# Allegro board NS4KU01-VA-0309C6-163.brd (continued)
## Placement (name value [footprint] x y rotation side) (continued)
M3  -  [M-MARK1]  58.34 139.41 0 top
M4  -  [M-MARK1]  36.34 18.21 0 top
M5  -  [M-MARK1]  137.11 31.49 0 top
M6  -  [M-MARK1]  151.3 138.56 0 top
M9  -  [M-MARK1]  151.56 138.56 180 bottom
M10  -  [M-MARK1]  6.9 138.56 180 bottom
M13  -  [M-MARK1]  13.74 15.61 180 bottom
M14  -  [M-MARK1]  137.16 20.69 180 bottom
NOREF  -  []  2.69 55.3 0 top
NOREF#2  -  [unnamed#2]  138.17 4 0 top
NOREF#3  -  [unnamed#2]  145.37 4 0 top
NOREF#4  -  [unnamed#2]  -5.27 11.02 0 top
NOREF#5  -  [unnamed#2]  0.73 9.02 0 top
NOREF#6  -  [unnamed#2]  4.64 4.18 0 top
NOREF#7  -  [unnamed#2]  5.84 6.14 0 top
NOREF#8  -  [unnamed#2]  140.57 6 0 top
NOREF#9  -  [unnamed#2]  136.97 4 0 top
NOREF#10  -  [unnamed#2]  -7.67 11.02 0 top
NOREF#11  -  [unnamed#2]  139.37 6 0 top
NOREF#12  -  [unnamed#2]  144.17 4 0 top
NOREF#13  -  [unnamed#2]  4.64 6.14 0 top
NOREF#14  -  [unnamed#2]  144.17 6 0 top
NOREF#15  -  [unnamed#2]  -8.87 9.02 0 top
NOREF#16  -  [unnamed#2]  142.97 4 0 top
NOREF#17  -  [unnamed#2]  -0.47 11.02 0 top
NOREF#18  -  [unnamed#2]  139.37 4 0 top
NOREF#19  -  [unnamed#2]  -8.87 11.02 0 top
NOREF#20  -  [unnamed#2]  158.69 8.2 0 top
NOREF#21  -  [unnamed#2]  146.57 4 0 top
NOREF#22  -  [unnamed#2]  -4.07 11.02 0 top
NOREF#23  -  [unnamed#2]  136.97 6 0 top
NOREF#24  -  []  43.24 -116.05 0 top
NOREF#25  -  [unnamed#2]  -2.87 9.02 0 top
NOREF#26  -  [unnamed#2]  140.57 4 0 top
NOREF#27  -  [unnamed#2]  138.17 6 0 top
NOREF#28  -  [unnamed#2]  146.57 6 0 top
NOREF#29  -  [unnamed#2]  -1.67 9.02 0 top
NOREF#30  -  [unnamed#2]  7.04 4.18 0 top
NOREF#31  -  [unnamed#2]  141.77 4 0 top
NOREF#32  -  [unnamed#2]  -7.67 9.02 0 top
NOREF#33  -  [unnamed#2]  145.37 6 0 top
NOREF#34  -  [unnamed#2]  -4.07 9.02 0 top
NOREF#35  -  [unnamed#2]  142.97 6 0 top
NOREF#36  -  [unnamed#2]  0.73 11.02 0 top
NOREF#37  -  [unnamed#2]  -6.47 11.02 0 top
NOREF#38  -  [unnamed#2]  -1.67 11.02 0 top
NOREF#39  -  [unnamed#2]  7.04 6.14 0 top
NOREF#40  -  [unnamed#2]  -6.47 9.02 0 top
NOREF#41  -  [unnamed#2]  -0.47 9.02 0 top
NOREF#42  -  [unnamed#2]  72.19 139.9 0 top
NOREF#43  -  [unnamed#2]  -2.87 11.02 0 top
NOREF#44  -  [unnamed#2]  141.77 6 0 top
NOREF#45  -  [unnamed#2]  134.41 9.53 0 top
NOREF#46  -  [unnamed#2]  -5.27 9.02 0 top
NOREF#47  -  [unnamed#2]  5.84 4.18 0 top
NOREF#48  -  []  2.69 55.3 180 bottom
PJP2  -  [TOPSHORT_20X30]  18.33 102.04 90 top
PJP6  -  [TOPSHORT_20X30]  46 139.5 180 top
PJP10  -  [TOPSHORT_20X30]  102.28 139.83 90 top
PJP11  -  [TOPSHORT_20X30]  58.57 137.15 270 bottom
PJP12  -  [TOPSHORT_20X30]  130.42 116.13 90 top
PJP17  -  [TOPOPEN_20X157]  68.78 76.21 0 bottom
PJP18  -  [TOPOPEN_20X157]  78.18 75.83 180 bottom
PJP36  -  [TOPSHORT_20X30]  22.44 44.31 90 bottom
PS3  SPR-P110-6V-1.1A-0805  [M-C0805]  144.19 106.69 90 top
Q1  MTDK5S6R-0-T1-G  [SOT363]  3.66 107.73 0 bottom
Q4  2N7002-7-F  [M-SOT23G]  54.38 59.55 0 top
Q6  LMBT3904LT1G  [M-SOT23A]  62.15 58.55 270 top
Q10  -  [M-SC70-5]  115.23 57.03 90 top
Q11  MTDK5S6R-0-T1-G  [SOT363]  107.49 59.6 0 top
Q12  2N7002-7-F  [M-SOT23G]  120.15 138.52 0 top
Q13  LMBT3904LT1G  [M-SOT23A]  117.98 53.83 90 top
Q14  2N7002-7-F  [M-SOT23G]  118.11 130.58 180 top
Q15  MTDK5S6R-0-T1-G  [SOT363]  124.61 74.48 0 top
Q16  MTDK5S6R-0-T1-G  [SOT363]  125.24 119.69 0 bottom
Q17  -  [M-SC70-5]  17.97 116.44 270 top
Q18  MTDK5S6R-0-T1-G  [SOT363]  128.6 136.28 0 bottom
Q19  2N7002-7-F  [M-SOT23G]  144.19 20.84 90 top
Q20  2N7002-7-F  [M-SOT23G]  30.19 79.17 0 top
Q21  @LMBT3904LT1G  [M-SOT23A]  119.48 138.44 270 bottom
Q22  @LMBT3904LT1G  [M-SOT23A]  113.46 138.44 90 bottom
Q24  MTDK5S6R-0-T1-G  [SOT363]  125.27 137.04 90 bottom
Q25  MTDK5S6R-0-T1-G  [SOT363]  108.58 135.94 90 bottom
Q26  2N7002-7-F  [M-SOT23G]  126.79 132.21 90 bottom
Q27  MTDK5S6R-0-T1-G  [SOT363]  130.6 119.77 180 bottom
Q28  2N7002-7-F  [M-SOT23G]  145.97 104.02 90 bottom
Q29  2N7002-7-F  [M-SOT23G]  145.97 100.85 90 bottom
Q30  2N7002-7-F  [M-SOT23G]  110.92 99.58 0 bottom
Q31  EMB20N03V  [PDFN-8P_B3X3_D65]  6.43 98.89 0 bottom
Q32  2N7002-7-F  [M-SOT23G]  145.97 97.54 90 bottom
Q33  2N7002-7-F  [M-SOT23G]  148 93.73 90 bottom
Q34  EMB20N03V  [PDFN-8P_B3X3_D65]  10.03 92.29 0 bottom
Q35  2N7002-7-F  [M-SOT23G]  17.61 65.58 0 top
Q36  2N7002-7-F  [M-SOT23G]  22.16 72.45 270 bottom
Q37  2N7002-7-F  [M-SOT23G]  22.79 69.09 90 bottom
Q38  2N7002-7-F  [M-SOT23G]  110.66 51.44 90 bottom
Q39  MTDK5S6R  [SOT363]  142.11 50.78 180 bottom
Q40  2N7002-7-F  [M-SOT23G]  143.55 31.63 180 bottom
Q41  EMB20N03V  [PDFN-8P_B3X3_D65]  73.45 34.3 180 top
Q42  EMB20N03V  [PDFN-8P_B3X3_D65]  78.15 34.3 0 top
Q43  -  [PQFN8-PPS]  56.21 39.89 90 top
Q44  -  [PQFN8-PPS]  64.69 35.57 0 top
Q45  -  [PQFN8-PPS]  28.24 65.97 90 top
Q46  -  [PQFN8-PPS]  34.67 66.07 180 top
Q47  EMB20N03V  [PDFN-8P_B3X3_D65]  88.08 37.86 90 top
Q48  EMB20N03V  [PDFN-8P_B3X3_D65]  96.21 37.47 0 top
Q49  2N7002-7-F  [M-SOT23G]  138.66 70.72 180 bottom
Q50  2N7002-7-F  [M-SOT23G]  138.63 66.99 180 bottom
Q51  2N7002-7-F  [M-SOT23G]  132.12 106.69 0 bottom
Q52  2N7002-7-F  [M-SOT23G]  123.69 138.24 270 top
Q53  2N7002-7-F  [M-SOT23G]  140.87 58.86 90 bottom
Q54  2N7002-7-F  [M-SOT23G]  134.01 72.06 270 top
Q55  LMBT3904LT1G  [M-SOT23A]  102.36 138.28 0 bottom
Q56  2N7002-7-F  [M-SOT23G]  99.09 136.25 0 bottom
Q57  2N7002-7-F  [M-SOT23G]  140.12 95.01 0 bottom
Q58  2N7002-7-F  [M-SOT23G]  140.08 100.02 180 bottom
Q59  MTDK5S6R  [SOT363]  132.15 76.59 180 top
Q60  -  [PQFN8-PPS]  48.46 40.01 270 top
Q61  EMB20N03V  [PDFN-8P_B3X3_D65]  140.63 107.96 270 top
Q62  -  [PQFN8-PPS]  42.62 47 270 top
Q63  -  [PQFN8-PPS]  42.63 46.98 90 bottom
Q151  2N7002-7-F  [M-SOT23G]  12.79 47.61 180 top
Q152  2N7002-7-F  [M-SOT23G]  9.55 47.61 180 top
Q156  VALUE*  [M-SOT23A]  26.91 79.17 0 top
R1  499-1-04  [M-R0402]  6.43 102.57 0 bottom
R2  499-1-04  [M-R0402]  5.51 108.23 90 bottom
R3  499-1-04  [M-R0402]  1.85 106.2 90 bottom
R4  499-1-04  [M-R0402]  3.73 110.49 90 bottom
R5  499-1-04  [M-R0402]  4.17 104.34 180 bottom
R6  499-1-04  [M-R0402]  8.3 97.67 270 top
R7  499-1-04  [M-R0402]  10.08 98.31 0 top
R8  499-1-04  [M-R0402]  10.2 99.96 270 top
R9  499-1-04  [M-R0402]  11.73 99.45 270 top
R10  499-1-04  [M-R0402]  11.98 128.4 0 top
R11  499-1-04  [M-R0402]  11.98 126.12 0 top
R12  499-1-04  [M-R0402]  11.98 125.1 180 top
R13  499-1-04  [M-R0402]  12.74 99.45 270 top
R14  499-1-04  [M-R0402]  13.89 99.45 270 top
R15  @1K-1-06  [M-R0603]  14.9 62.18 180 top
R16  @1K-1-06  [M-R0603]  14.9 60.75 180 top
R17  @1K-1-06  [M-R0603]  15.08 100.26 90 top
R18  499-1-04  [M-R0402]  20.14 114.77 0 top
R19  499-1-04  [M-R0402]  16.3 131.33 90 top
R20  @1K-1-06  [M-R0603]  16.48 100.26 90 top
R21  499-1-04  [M-R0402]  16.91 62.16 270 top
R22  499-1-04  [M-R0402]  16.79 118.8 180 top
R23  499-1-04  [M-R0402]  20.22 62.16 270 top
R24  499-1-04  [M-R0402]  18.71 131.33 270 top
R25  @1K-1-06  [M-R0603]  18.84 99.07 270 top
R26  @1K-1-06  [M-R0603]  19.35 91.83 0 top
R27  499-1-04  [M-R0402]  23.64 62.16 270 top
R28  499-1-04  [M-R0402]  19.73 131.33 90 top
R29  499-1-04  [M-R0402]  19.73 97.16 180 top
R30  499-1-04  [M-R0402]  19.73 95.89 0 top
R31  499-1-04  [M-R0402]  20.24 99.32 90 top
R32  499-1-04  [M-R0402]  12.82 113.67 0 top
R33  499-1-04  [M-R0402]  20.87 119.77 0 top
R34  499-1-04  [M-R0402]  20.87 118.75 180 top
R35  499-1-04  [M-R0402]  20.87 117.74 180 top
R36  499-1-04  [M-R0402]  23.54 125.36 0 top
R37  499-1-04  [M-R0402]  23.54 124.34 0 top
R38  499-1-04  [M-R0402]  25.19 125.61 270 top
R41  499-1-04  [M-R0402]  17.01 85.38 90 bottom
R42  499-1-04  [M-R0402]  142.95 26.29 0 top
R43  @1K-1-06  [M-R0603]  29.99 125.38 270 top
R46  @1K-1-06  [M-R0603]  33.04 124.77 180 top
R50  499-1-04  [M-R0402]  142.87 45.8 0 top
R51  @1K-1-06  [M-R0603]  36.62 129.29 0 top
R52  499-1-04  [M-R0402]  18.49 133.18 180 bottom
R53  499-1-04  [M-R0402]  39.9 130.61 270 top
R54  499-1-04  [M-R0402]  16.2 133.18 180 bottom
R55  @1K-1-06  [M-R0603]  143.91 52.51 270 bottom
R56  499-1-04  [M-R0402]  23.57 133.36 180 bottom
R57  499-1-04  [M-R0402]  25.85 133.36 180 bottom
R58  499-1-04  [M-R0402]  116.79 22.11 0 bottom
R59  499-1-04  [M-R0402]  43.92 138.95 90 top
R60  499-1-04  [M-R0402]  42.06 129.85 270 top
R61  499-1-04  [M-R0402]  119.07 22.11 180 bottom
R62  499-1-04  [M-R0402]  116.79 18.68 0 bottom
R63  499-1-04  [M-R0402]  45.49 130.1 90 top
R64  499-1-04  [M-R0402]  119.07 18.68 180 bottom
R65  499-1-04  [M-R0402]  125.68 23.25 90 top
R66  499-1-04  [M-R0402]  87.33 129.46 180 bottom
R67  499-1-04  [M-R0402]  89.05 128.83 90 bottom
R68  499-1-04  [M-R0402]  90.26 128.83 270 bottom
R69  499-1-04  [M-R0402]  57.83 89.06 270 bottom
R70  499-1-04  [M-R0402]  53.96 89.12 270 bottom
R71  499-1-04  [M-R0402]  52.16 88.57 0 bottom
R72  499-1-04  [M-R0402]  55.8 90.83 0 bottom
R73  499-1-04  [M-R0402]  52.16 89.78 180 bottom
R74  499-1-04  [M-R0402]  39.16 93.88 0 bottom
R75  499-1-04  [M-R0402]  38.78 82.39 0 top
R76  499-1-04  [M-R0402]  37.74 100.83 0 top
R77  499-1-04  [M-R0402]  38.84 112.93 180 bottom
R79  499-1-04  [M-R0402]  63.35 63.89 0 bottom
R80  499-1-04  [M-R0402]  54.44 57.14 180 top
R81  499-1-04  [M-R0402]  36.18 94.96 90 bottom
R82  499-1-04  [M-R0402]  55.72 61.37 90 top
R83  499-1-04  [M-R0402]  56.94 58.94 270 top
R85  499-1-04  [M-R0402]  57.96 58.94 90 top
R86  499-1-04  [M-R0402]  56.92 61.37 270 top
R87  499-1-04  [M-R0402]  37.38 94.96 90 bottom
R88  499-1-04  [M-R0402]  58.06 61.35 270 bottom
R89  499-1-04  [M-R0402]  58.98 58.93 270 bottom
R90  499-1-04  [M-R0402]  131.41 112.37 180 top
R91  499-1-04  [M-R0402]  133.89 112.29 180 top
R92  499-1-04  [M-R0402]  61.26 61.35 90 top
R93  499-1-04  [M-R0402]  34.12 94.67 0 top
R94  499-1-04  [M-R0402]  62.4 61.35 270 top
R95  499-1-04  [M-R0402]  63.42 61.35 270 top
R96  499-1-04  [M-R0402]  133.85 110.09 0 top
R97  499-1-04  [M-R0402]  133.89 111.27 180 top
R98  499-1-04  [M-R0402]  65.58 61.35 270 top
R99  499-1-04  [M-R0402]  65.7 58.81 270 top
R100  499-1-04  [M-R0402]  66.72 61.35 90 top
R101  499-1-04  [M-R0402]  66.72 58.81 90 top
R102  @1K-1-06  [M-R0603]  66.72 57.03 0 top
R103  499-1-04  [M-R0402]  67.86 61.35 90 top
R104  499-1-04  [M-R0402]  67.86 58.81 270 top
R105  499-1-04  [M-R0402]  70.02 61.4 90 top
R106  @1K-1-06  [M-R0603]  71.65 131.25 180 top
R107  499-1-04  [M-R0402]  119.07 19.82 180 bottom
R108  499-1-04  [M-R0402]  76.37 59.55 270 top
R109  499-1-04  [M-R0402]  81.2 60.71 180 top
R110  499-1-04  [M-R0402]  87.73 50.68 180 top
R111  499-1-04  [M-R0402]  119.07 20.96 180 bottom
R112  499-1-04  [M-R0402]  87.73 51.95 0 top
R113  499-1-04  [M-R0402]  113.84 59.06 180 top
R114  499-1-04  [M-R0402]  90.47 139.07 0 top
R115  499-1-04  [M-R0402]  100.1 139.12 90 bottom
R116  499-1-04  [M-R0402]  11.99 115.22 180 top
R117  499-1-04  [M-R0402]  116.12 59.06 180 top
R118  499-1-04  [M-R0402]  93.04 61.35 270 top
R119  499-1-04  [M-R0402]  118.41 58.3 0 top
R120  499-1-04  [M-R0402]  119.07 17.54 180 bottom
R121  499-1-04  [M-R0402]  94.28 61.35 90 top
R122  499-1-04  [M-R0402]  94.94 133.28 270 top
R123  499-1-04  [M-R0402]  95.42 61.35 90 top
R124  499-1-04  [M-R0402]  96.56 61.35 90 top
R125  @1K-1-06  [M-R0603]  96.59 52.71 270 top
R126  499-1-04  [M-R0402]  97.71 61.35 90 top
R127  499-1-04  [M-R0402]  102.03 61.35 90 top
R128  499-1-04  [M-R0402]  99.56 61.32 270 top
R129  499-1-04  [M-R0402]  99.99 138.82 180 top
R130  499-1-04  [M-R0402]  100.12 135.9 180 top
R131  499-1-04  [M-R0402]  103.17 61.35 270 top
R132  499-1-04  [M-R0402]  110.9 9.22 90 top
R133  499-1-04  [M-R0402]  111.98 9.22 90 top
R134  499-1-04  [M-R0402]  113.16 9.21 90 top
R135  499-1-04  [M-R0402]  104.82 87.08 0 top
R136  499-1-04  [M-R0402]  104.82 85.86 180 top
R138  499-1-04  [M-R0402]  104.95 74.81 0 top
R139  499-1-04  [M-R0402]  104.82 66.94 180 top
R140  499-1-04  [M-R0402]  34.5 98.86 90 bottom
R141  499-1-04  [M-R0402]  104.95 73.16 0 top
R142  499-1-04  [M-R0402]  104.95 72.14 0 top
R143  499-1-04  [M-R0402]  104.95 71.13 180 top
R144  499-1-04  [M-R0402]  104.47 63.51 270 top
R145  @1K-1-06  [M-R0603]  105.28 53.66 270 top
R147  499-1-04  [M-R0402]  106.47 69.1 90 top
R148  499-1-04  [M-R0402]  106.72 62.49 90 top
R149  499-1-04  [M-R0402]  106.85 56.9 90 top
R150  499-1-04  [M-R0402]  106.98 87.38 90 top
R151  499-1-04  [M-R0402]  108.12 74.86 0 top
R152  499-1-04  [M-R0402]  107.23 71.13 0 top
R153  499-1-04  [M-R0402]  107.23 66.56 180 top
R154  499-1-04  [M-R0402]  107.31 65.06 0 top
R155  499-1-04  [M-R0402]  107.36 73.16 180 top
R157  499-1-04  [M-R0402]  107.87 62.49 270 top
R158  499-1-04  [M-R0402]  107.99 56.9 90 top
R159  499-1-04  [M-R0402]  108.12 87.41 270 top
R160  499-1-04  [M-R0402]  108.38 90.18 0 top
R161  499-1-04  [M-R0402]  108.5 89.03 0 top
R163  499-1-04  [M-R0402]  109.01 62.49 270 top
R164  499-1-04  [M-R0402]  109.5 56.82 270 top
R165  @1K-1-06  [M-R0603]  104.66 130.82 180 top
R167  499-1-04  [M-R0402]  111.3 72.02 90 top
R168  499-1-04  [M-R0402]  110.28 75.06 90 top
R170  499-1-04  [M-R0402]  111.3 75.06 270 top
R171  499-1-04  [M-R0402]  112.31 72.02 90 top
R173  499-1-04  [M-R0402]  110.15 72.02 90 top
R174  499-1-04  [M-R0402]  120.78 134.61 0 top
R176  499-1-04  [M-R0402]  113.33 72.02 270 top
R177  499-1-04  [M-R0402]  113.69 74.86 270 top
R179  499-1-04  [M-R0402]  114.83 74.86 270 top
R180  499-1-04  [M-R0402]  114.85 73.41 180 top
R182  @1K-1-06  [M-R0603]  117.98 132.97 180 top
R184  499-1-04  [M-R0402]  118.33 139.86 0 top
R185  499-1-04  [M-R0402]  117.55 91.85 0 top
R187  499-1-04  [M-R0402]  117.77 99.7 0 top
R188  499-1-04  [M-R0402]  117.77 98.56 0 top
R189  499-1-04  [M-R0402]  115.8 131.67 270 top
R190  499-1-04  [M-R0402]  119.3 80.53 90 top
R191  499-1-04  [M-R0402]  119.3 92.97 0 top
R192  499-1-04  [M-R0402]  119.42 75.83 270 top
R193  499-1-04  [M-R0402]  119.42 73.67 90 top
R194  499-1-04  [M-R0402]  140.6 61.12 0 bottom
R195  499-1-04  [M-R0402]  120.31 98.56 0 top
R196  499-1-04  [M-R0402]  120.57 75.83 270 top
R197  499-1-04  [M-R0402]  120.57 74.94 270 top
R198  @1K-1-06  [M-R0603]  123.95 112.35 0 bottom
R199  499-1-04  [M-R0402]  121.53 53.7 270 top
R200  499-1-04  [M-R0402]  121.72 75.83 90 top
R201  499-1-04  [M-R0402]  121.72 74.94 90 top
R202  499-1-04  [M-R0402]  122.47 72.65 90 top
R204  499-1-04  [M-R0402]  124.12 72.14 0 top
R205  499-1-04  [M-R0402]  124.79 76.94 180 top
R207  499-1-04  [M-R0402]  115.23 122.65 180 bottom
R210  499-1-04  [M-R0402]  128.12 119.65 180 top
R211  499-1-04  [M-R0402]  125.69 71.63 90 top
R212  499-1-04  [M-R0402]  122.86 74.93 270 top
R213  499-1-04  [M-R0402]  126.28 63.25 0 top
R214  499-1-04  [M-R0402]  126.28 62.24 0 top
R215  499-1-04  [M-R0402]  109.5 59.11 90 top
R216  499-1-04  [M-R0402]  126.54 60.33 90 top
R217  499-1-04  [M-R0402]  126.92 67.32 270 top
R218  499-1-04  [M-R0402]  127.55 60.33 90 top
R219  499-1-04  [M-R0402]  128.19 118.5 0 top
R220  499-1-04  [M-R0402]  119.53 115.12 270 bottom
R221  499-1-04  [M-R0402]  142.15 70.42 270 bottom
R222  499-1-04  [M-R0402]  128.17 113.85 0 top
R223  499-1-04  [M-R0402]  128.47 80.86 90 top
R224  499-1-04  [M-R0402]  128.47 79.99 90 top
R225  499-1-04  [M-R0402]  128.57 60.33 90 top
R226  499-1-04  [M-R0402]  82.21 124.43 180 bottom
R227  499-1-04  [M-R0402]  94.21 125.44 180 bottom
R228  499-1-04  [M-R0402]  128.42 119.18 270 bottom
R229  499-1-04  [M-R0402]  129.58 60.33 270 top
R230  @1K-1-06  [M-R0603]  112.69 119.92 90 bottom
R231  499-1-04  [M-R0402]  128.29 116.21 0 top
R232  499-1-04  [M-R0402]  130.51 80.86 90 top
R233  499-1-04  [M-R0402]  130.51 79.99 90 top
R234  499-1-04  [M-R0402]  127.28 119.18 270 bottom
R235  @1K-1-06  [M-R0603]  142.39 104.1 270 top
R236  499-1-04  [M-R0402]  141.01 70.42 270 bottom
R237  499-1-04  [M-R0402]  94.21 126.65 0 bottom
R238  499-1-04  [M-R0402]  131.65 80.86 270 top
R239  499-1-04  [M-R0402]  132.61 120.83 90 bottom
R240  499-1-04  [M-R0402]  132.67 80.86 90 top
R241  499-1-04  [M-R0402]  132.89 64.9 180 top
R242  499-1-04  [M-R0402]  132.89 63.89 180 top
R243  499-1-04  [M-R0402]  132.89 62.75 180 top
R244  499-1-04  [M-R0402]  133.75 120.83 90 bottom
R245  @1K-1-06  [M-R0603]  133.65 69.6 0 top
R246  499-1-04  [M-R0402]  113.65 124.17 90 bottom
R247  499-1-04  [M-R0402]  115.23 123.85 0 bottom
R248  499-1-04  [M-R0402]  134.66 45.98 90 top
R249  499-1-04  [M-R0402]  6.38 62.75 0 top
R250  499-1-04  [M-R0402]  131.32 113.44 90 bottom
R251  499-1-04  [M-R0402]  134.89 86.67 90 top
R252  499-1-04  [M-R0402]  134.89 85.78 270 top
R253  499-1-04  [M-R0402]  130.81 111.66 0 bottom
R254  499-1-04  [M-R0402]  112.5 124.17 270 bottom
R255  499-1-04  [M-R0402]  135.68 45.98 90 top
R256  499-1-04  [M-R0402]  36.92 100.06 90 bottom
R257  499-1-04  [M-R0402]  28.75 94.71 90 top
R258  499-1-04  [M-R0402]  136.07 70.16 90 top
R260  499-1-04  [M-R0402]  130.3 113.44 90 bottom
R261  499-1-04  [M-R0402]  136.21 86.67 90 top
R262  499-1-04  [M-R0402]  136.21 85.78 270 top
R263  499-1-04  [M-R0402]  129.94 111.66 180 bottom
R264  @1K-1-06  [M-R0603]  50.12 131.56 180 top
R265  499-1-04  [M-R0402]  136.7 45.98 90 top
R266  499-1-04  [M-R0402]  30.18 100.19 270 bottom
R267  499-1-04  [M-R0402]  28.24 99.91 270 bottom
R268  499-1-04  [M-R0402]  129.28 113.44 90 bottom
R269  499-1-04  [M-R0402]  30.52 100.42 0 top
R270  499-1-04  [M-R0402]  137.71 45.98 90 top
R271  499-1-04  [M-R0402]  29.76 94.71 90 top
R272  499-1-04  [M-R0402]  29.76 97.88 90 bottom
R273  499-1-04  [M-R0402]  126.65 135.47 270 top
R274  499-1-04  [M-R0402]  26.4 94.77 90 top
R275  499-1-04  [M-R0402]  138.73 45.98 90 top
R276  499-1-04  [M-R0402]  27.52 97.52 270 bottom
R277  499-1-04  [M-R0402]  142.42 123.03 270 top
R278  499-1-04  [M-R0402]  44.47 124.01 180 top
R279  499-1-04  [M-R0402]  24.49 97.5 90 bottom
R280  499-1-04  [M-R0402]  139.72 45.98 90 top
R281  499-1-04  [M-R0402]  27.54 94.71 90 top
R282  499-1-04  [M-R0402]  141.04 66.68 270 bottom
R283  499-1-04  [M-R0402]  142.64 68.51 270 top
R284  499-1-04  [M-R0402]  143.43 123.03 270 top
R285  499-1-04  [M-R0402]  130.42 69.05 0 top
R286  499-1-04  [M-R0402]  138.55 25.68 0 top
R287  499-1-04  [M-R0402]  136.67 78.92 90 top
R288  499-1-04  [M-R0402]  142.65 116.61 180 top
R289  499-1-04  [M-R0402]  142.65 115.6 180 top
R290  499-1-04  [M-R0402]  144.7 123.03 90 top
R291  499-1-04  [M-R0402]  145.72 123.03 90 top
R292  499-1-04  [M-R0402]  142.56 113.69 180 top
R293  499-1-04  [M-R0402]  142.56 112.68 180 top
R294  499-1-04  [M-R0402]  136.34 66.1 90 bottom
R295  499-1-04  [M-R0402]  140.61 50.73 270 top
R296  499-1-04  [M-R0402]  142.95 60 180 top
R297  499-1-04  [M-R0402]  142.92 58.83 180 top
R298  499-1-04  [M-R0402]  142.65 118.72 180 top
R299  499-1-04  [M-R0402]  142.65 117.71 180 top
R300  499-1-04  [M-R0402]  141.31 79.44 180 top
R301  499-1-04  [M-R0402]  145.08 100.46 0 top
R302  499-1-04  [M-R0402]  145.08 97.42 0 top
R303  499-1-04  [M-R0402]  145.08 94.37 0 top
R304  499-1-04  [M-R0402]  147.49 102.88 180 top
R305  499-1-04  [M-R0402]  147.49 99.96 180 top
R306  499-1-04  [M-R0402]  147.62 97.29 180 top
R307  499-1-04  [M-R0402]  147.62 92.21 180 top
R308  499-1-04  [M-R0402]  147.75 94.75 180 top
R309  499-1-04  [M-R0402]  125.42 139.3 270 bottom
R310  499-1-04  [M-R0402]  92.22 139.5 270 bottom
R311  499-1-04  [M-R0402]  90.98 139.45 90 bottom
R312  499-1-04  [M-R0402]  88.69 139.45 90 bottom
R313  499-1-04  [M-R0402]  124.15 139.36 90 bottom
R314  499-1-04  [M-R0402]  122.35 139.33 180 bottom
R315  499-1-04  [M-R0402]  96.18 139.33 180 bottom
R316  499-1-04  [M-R0402]  97.97 139.15 90 bottom
R317  499-1-04  [M-R0402]  117.01 138.56 90 bottom
R318  499-1-04  [M-R0402]  116 138.56 90 bottom
R319  499-1-04  [M-R0402]  122.35 138.31 0 bottom
R320  499-1-04  [M-R0402]  141.31 78.42 180 top
R321  499-1-04  [M-R0402]  94.79 136.79 90 bottom
R322  499-1-04  [M-R0402]  114.53 136.15 0 bottom
R323  499-1-04  [M-R0402]  109.5 138.54 270 bottom
R324  499-1-04  [M-R0402]  122.35 136.28 180 bottom
R325  499-1-04  [M-R0402]  114.53 135.06 0 bottom
R326  499-1-04  [M-R0402]  122.35 135.26 180 bottom
R327  499-1-04  [M-R0402]  108.4 138.53 90 bottom
R328  499-1-04  [M-R0402]  125.65 135.26 180 bottom
R329  @1K-1-06  [M-R0603]  36.24 136.83 270 bottom
R330  499-1-04  [M-R0402]  146.43 134.12 180 bottom
R331  499-1-04  [M-R0402]  107.21 138.54 270 bottom
R332  499-1-04  [M-R0402]  124.5 133.61 90 bottom
R333  499-1-04  [M-R0402]  122.35 133.23 180 bottom
R334  499-1-04  [M-R0402]  114.55 132.41 0 bottom
R335  499-1-04  [M-R0402]  32.15 97.02 90 bottom
R336  499-1-04  [M-R0402]  38.76 126.99 180 top
R337  499-1-04  [M-R0402]  32.05 129.29 180 bottom
R338  499-1-04  [M-R0402]  30.14 129.04 270 bottom
R339  499-1-04  [M-R0402]  27.1 129.04 90 bottom
R340  499-1-04  [M-R0402]  26.08 129.04 270 bottom
R341  499-1-04  [M-R0402]  25.25 94.77 90 top
R342  499-1-04  [M-R0402]  33.68 96.76 90 bottom
R343  499-1-04  [M-R0402]  27.03 99.91 270 bottom
R344  499-1-04  [M-R0402]  35.71 98.86 90 bottom
R345  499-1-04  [M-R0402]  35.67 96.8 180 bottom
R346  499-1-04  [M-R0402]  135.55 126.5 270 bottom
R347  499-1-04  [M-R0402]  134.41 126.5 90 bottom
R348  499-1-04  [M-R0402]  128.19 126.5 270 bottom
R349  499-1-04  [M-R0402]  129.2 126.5 270 bottom
R350  499-1-04  [M-R0402]  26.08 125.74 0 bottom
R351  499-1-04  [M-R0402]  124.63 123.83 180 bottom
R352  499-1-04  [M-R0402]  130.32 122.23 0 bottom
R353  499-1-04  [M-R0402]  124.63 122.82 180 bottom
R354  499-1-04  [M-R0402]  32.79 98.86 180 bottom
R355  499-1-04  [M-R0402]  31.01 94.73 90 top
R356  499-1-04  [M-R0402]  29.89 119.9 270 bottom
R357  499-1-04  [M-R0402]  29.1 95.3 90 bottom
R358  499-1-04  [M-R0402]  30.98 118.93 270 bottom
R359  499-1-04  [M-R0402]  139.94 102.4 0 bottom
R360  499-1-04  [M-R0402]  31.03 98.07 270 bottom
R361  499-1-04  [M-R0402]  32.24 95.09 90 top
R362  499-1-04  [M-R0402]  27.25 118.47 270 bottom
R363  499-1-04  [M-R0402]  26.31 97.21 90 bottom
R364  499-1-04  [M-R0402]  25.8 99.94 270 bottom
R365  499-1-04  [M-R0402]  120.16 88.7 180 top
R366  499-1-04  [M-R0402]  130.45 116.26 0 bottom
R367  499-1-04  [M-R0402]  130.45 117.4 0 bottom
R368  499-1-04  [M-R0402]  73.83 119.03 90 bottom
R369  499-1-04  [M-R0402]  137.31 117.66 0 bottom
R370  499-1-04  [M-R0402]  138.19 113.11 0 bottom
R371  499-1-04  [M-R0402]  7.66 113.8 270 bottom
R372  499-1-04  [M-R0402]  72.62 119.03 90 bottom
R373  499-1-04  [M-R0402]  17.06 113.04 270 bottom
R374  499-1-04  [M-R0402]  16.05 113.04 270 bottom
R375  499-1-04  [M-R0402]  15.03 113.04 270 bottom
R376  499-1-04  [M-R0402]  14.01 113.04 270 bottom
R377  499-1-04  [M-R0402]  44.47 122.74 0 top
R378  499-1-04  [M-R0402]  19.48 110.6 180 bottom
R379  499-1-04  [M-R0402]  19.48 109.58 180 bottom
R380  499-1-04  [M-R0402]  8.71 108.77 0 bottom
R381  499-1-04  [M-R0402]  8.71 107.75 0 bottom
R382  499-1-04  [M-R0402]  19.12 106.87 0 bottom
R383  499-1-04  [M-R0402]  8.71 106.74 180 bottom
R384  499-1-04  [M-R0402]  8.71 105.72 0 bottom
R385  499-1-04  [M-R0402]  142.28 105.04 180 bottom
R386  499-1-04  [M-R0402]  8.68 103.74 0 bottom
R387  499-1-04  [M-R0402]  148.61 103.18 90 bottom
R388  499-1-04  [M-R0402]  142.28 102.62 0 bottom
R389  499-1-04  [M-R0402]  19.12 102.17 180 bottom
R390  499-1-04  [M-R0402]  19.12 101.15 0 bottom
R391  499-1-04  [M-R0402]  148.51 100.21 270 bottom
R392  499-1-04  [M-R0402]  101.64 100.08 0 bottom
R395  499-1-04  [M-R0402]  107.36 99.32 0 bottom
R396  499-1-04  [M-R0402]  142.54 98.94 90 bottom
R397  499-1-04  [M-R0402]  12.87 98.69 180 bottom
R398  499-1-04  [M-R0402]  10.64 98.69 0 bottom
R399  499-1-04  [M-R0402]  107.36 98.31 0 bottom
R400  499-1-04  [M-R0402]  148.51 97.92 270 bottom
R401  499-1-04  [M-R0402]  15.67 97.92 180 bottom
R402  499-1-04  [M-R0402]  10.64 97.59 0 bottom
R403  499-1-04  [M-R0402]  102.15 97.16 90 bottom
R404  499-1-04  [M-R0402]  101.14 97.16 270 bottom
R405  499-1-04  [M-R0402]  104.31 96.65 0 bottom
R406  499-1-04  [M-R0402]  113.07 96.53 270 bottom
R407  499-1-04  [M-R0402]  111.93 96.53 270 bottom
R408  499-1-04  [M-R0402]  110.92 96.53 90 bottom
R409  499-1-04  [M-R0402]  109.9 96.53 270 bottom
R410  499-1-04  [M-R0402]  108.88 96.53 270 bottom
R411  499-1-04  [M-R0402]  107.87 96.53 270 bottom
R412  499-1-04  [M-R0402]  19.86 95.89 0 bottom
R413  499-1-04  [M-R0402]  104.82 94.88 90 bottom
R414  499-1-04  [M-R0402]  103.8 94.88 270 bottom
R416  499-1-04  [M-R0402]  99.61 94.88 90 bottom
R418  @1K-1-06  [M-R0603]  20.11 94.24 180 bottom
R419  -  [M-R1206]  6.8 93.94 270 bottom
R420  499-1-04  [M-R0402]  94.66 93.73 90 bottom
R421  499-1-04  [M-R0402]  113.2 92.84 270 bottom
R422  499-1-04  [M-R0402]  100.25 92.72 180 bottom
R423  499-1-04  [M-R0402]  144.06 93.23 270 bottom
R424  499-1-04  [M-R0402]  103.68 92.59 0 bottom
R425  499-1-04  [M-R0402]  111.96 92.85 90 bottom
R426  499-1-04  [M-R0402]  110.92 92.21 90 bottom
R427  499-1-04  [M-R0402]  109.77 92.21 90 bottom
R428  499-1-04  [M-R0402]  96.44 91.83 90 bottom
R429  499-1-04  [M-R0402]  108.63 91.45 90 bottom
R430  499-1-04  [M-R0402]  107.49 91.45 90 bottom
R431  499-1-04  [M-R0402]  106.34 91.45 270 bottom
R432  499-1-04  [M-R0402]  105.33 91.45 90 bottom
R434  499-1-04  [M-R0402]  103.55 91.19 180 bottom
R435  499-1-04  [M-R0402]  100.25 91.19 0 bottom
R436  499-1-04  [M-R0402]  98.6 90.69 90 bottom
R437  499-1-04  [M-R0402]  100.25 90.05 180 bottom
R438  499-1-04  [M-R0402]  97.07 90.05 180 bottom
R439  499-1-04  [M-R0402]  91.99 90.05 180 bottom
R440  499-1-04  [M-R0402]  83.29 90.26 90 bottom
R441  499-1-04  [M-R0402]  105.84 89.09 180 bottom
R442  499-1-04  [M-R0402]  103.68 89.09 0 bottom
R443  499-1-04  [M-R0402]  100.25 89.03 180 bottom
R448  499-1-04  [M-R0402]  102.03 88.53 270 bottom
R449  499-1-04  [M-R0402]  97.58 88.4 90 bottom
R450  499-1-04  [M-R0402]  95.6 87.07 180 bottom
R451  499-1-04  [M-R0402]  100.25 88.02 180 bottom
R452  499-1-04  [M-R0402]  92.56 87.43 180 bottom
R453  499-1-04  [M-R0402]  105.45 61.2 270 top
R454  499-1-04  [M-R0402]  100.25 87 180 bottom
R455  499-1-04  [M-R0402]  55.42 86.88 180 bottom
R456  499-1-04  [M-R0402]  107.39 87.64 180 bottom
R457  499-1-04  [M-R0402]  106.98 86.49 0 bottom
R460  499-1-04  [M-R0402]  100.25 85.99 180 bottom
R461  499-1-04  [M-R0402]  106.98 85.22 180 bottom
R462  499-1-04  [M-R0402]  133.3 124.5 0 top
R463  499-1-04  [M-R0402]  103.93 85.22 180 bottom
R464  499-1-04  [M-R0402]  100.25 84.97 180 bottom
R465  499-1-04  [M-R0402]  103.93 84.08 180 bottom
R466  499-1-04  [M-R0402]  100.25 83.83 0 bottom
R467  499-1-04  [M-R0402]  100.25 82.81 180 bottom
R469  499-1-04  [M-R0402]  76.37 81.16 0 bottom
R471  -  [M-R1206]  9.19 79.76 0 bottom
R472  499-1-04  [M-R0402]  83.48 79.13 270 bottom
R473  499-1-04  [M-R0402]  112.19 78.75 0 bottom
R474  499-1-04  [M-R0402]  109.98 78.49 0 bottom
R475  499-1-04  [M-R0402]  115.85 74.86 270 top
R476  499-1-04  [M-R0402]  87.04 78.37 90 bottom
R477  @1K-1-06  [M-R0603]  65.45 78.37 0 bottom
R478  499-1-04  [M-R0402]  103.04 78.11 180 bottom
R479  499-1-04  [M-R0402]  107.56 78.06 180 bottom
R480  @1K-1-06  [M-R0603]  85.9 77.86 90 bottom
R481  499-1-04  [M-R0402]  87.55 76.72 0 bottom
R482  499-1-04  [M-R0402]  101.14 75.83 90 bottom
R483  499-1-04  [M-R0402]  100.12 75.83 270 bottom
R484  499-1-04  [M-R0402]  85.01 75.45 0 bottom
R485  499-1-04  [M-R0402]  13.61 71.56 0 top
R486  499-1-04  [M-R0402]  94.41 74.3 180 bottom
R487  499-1-04  [M-R0402]  87.17 73.67 0 bottom
R488  499-1-04  [M-R0402]  84.88 73.67 180 bottom
R489  499-1-04  [M-R0402]  101.26 73.16 0 bottom
R490  499-1-04  [M-R0402]  16.02 72.57 180 top
R491  499-1-04  [M-R0402]  92.53 66.3 90 bottom
R492  499-1-04  [M-R0402]  66.16 68.36 0 bottom
R493  499-1-04  [M-R0402]  72.08 68.34 180 bottom
R494  499-1-04  [M-R0402]  20.44 69.85 0 top
R495  499-1-04  [M-R0402]  18.31 72.57 180 top
R496  499-1-04  [M-R0402]  98.47 68.16 90 bottom
R497  499-1-04  [M-R0402]  64.43 67.95 90 bottom
R498  499-1-04  [M-R0402]  63.29 67.95 90 bottom
R499  499-1-04  [M-R0402]  62.15 67.95 90 bottom
R500  499-1-04  [M-R0402]  100.28 81.8 180 bottom
R501  499-1-04  [M-R0402]  58.97 67.83 90 bottom
R502  499-1-04  [M-R0402]  57.58 67.83 270 bottom
R503  499-1-04  [M-R0402]  100.28 80.53 180 bottom
R504  499-1-04  [M-R0402]  105.48 67.19 270 bottom
R505  499-1-04  [M-R0402]  100.5 67.32 180 bottom
R506  499-1-04  [M-R0402]  92.66 68.46 90 bottom
R507  499-1-04  [M-R0402]  14.8 66.68 0 top
R508  499-1-04  [M-R0402]  58.97 65.54 270 bottom
R509  499-1-04  [M-R0402]  14.8 65.54 180 top
R510  499-1-04  [M-R0402]  12.39 65.41 180 top
R511  499-1-04  [M-R0402]  128.47 139.84 180 bottom
R512  499-1-04  [M-R0402]  128.47 138.57 0 bottom
R513  499-1-04  [M-R0402]  17.22 68.22 180 top
R514  @1K-1-06  [M-R0603]  12.01 66.68 180 top
R515  499-1-04  [M-R0402]  22.92 65.67 0 bottom
R516  499-1-04  [M-R0402]  18.73 72.14 90 bottom
R517  499-1-04  [M-R0402]  22.92 64.49 0 bottom
R518  499-1-04  [M-R0402]  128.57 53.6 270 bottom
R519  499-1-04  [M-R0402]  101.39 51.01 90 bottom
R520  499-1-04  [M-R0402]  97.33 51.01 270 bottom
R521  499-1-04  [M-R0402]  96.21 51.01 90 bottom
R522  499-1-04  [M-R0402]  140.61 56.57 0 bottom
R523  499-1-04  [M-R0402]  142.08 53.73 270 bottom
R524  499-1-04  [M-R0402]  141.07 53.73 270 bottom
R525  499-1-04  [M-R0402]  96.97 60.97 180 bottom
R526  499-1-04  [M-R0402]  99.26 60.97 0 bottom
R527  499-1-04  [M-R0402]  132.15 74.3 0 top
R528  499-1-04  [M-R0402]  59.19 58.92 90 top
R529  499-1-04  [M-R0402]  108.78 78.13 180 top
R530  499-1-04  [M-R0402]  108.28 50.81 270 bottom
R531  499-1-04  [M-R0402]  106.5 78.11 0 top
R532  @1K-1-06  [M-R0603]  110.92 51.44 0 bottom
R533  499-1-04  [M-R0402]  146.6 46.49 270 bottom
R534  499-1-04  [M-R0402]  145.59 46.49 90 bottom
R537  499-1-04  [M-R0402]  142.92 44.1 0 top
R539  499-1-04  [M-R0402]  110.59 41.69 90 bottom
R540  499-1-04  [M-R0402]  148.74 44.15 270 bottom
R541  499-1-04  [M-R0402]  146.7 44.15 270 bottom
R542  499-1-04  [M-R0402]  142.54 39.22 270 top
R545  499-1-04  [M-R0402]  142.9 32.21 0 top
R546  499-1-04  [M-R0402]  153.59 43.95 270 bottom
R547  499-1-04  [M-R0402]  152.57 43.95 90 bottom
R548  499-1-04  [M-R0402]  111.61 41.69 90 bottom
R549  @1K-1-06  [M-R0603]  91.51 36.71 270 top
R550  499-1-04  [M-R0402]  144.34 43.34 270 bottom
R551  499-1-04  [M-R0402]  143.33 43.34 90 bottom
R552  499-1-04  [M-R0402]  142.31 43.34 90 bottom
R553  499-1-04  [M-R0402]  142.9 29.7 0 top
R554  499-1-04  [M-R0402]  142.95 27.44 0 top
R557  499-1-04  [M-R0402]  130.12 77.1 90 top
R558  499-1-04  [M-R0402]  6.43 65.1 0 top
R559  499-1-04  [M-R0402]  6.44 64.07 0 top
R561  499-1-04  [M-R0402]  134.06 74.81 90 top
R562  @1K-1-06  [M-R0603]  93.16 6.23 0 bottom
R563  @1K-1-06  [M-R0603]  80.08 4.96 90 bottom
R564  499-1-04  [M-R0402]  149.65 41.16 270 bottom
R565  499-1-04  [M-R0402]  111.71 38.11 270 bottom
R566  499-1-04  [M-R0402]  110.44 38.11 270 bottom
R567  499-1-04  [M-R0402]  111.71 39 90 bottom
R568  499-1-04  [M-R0402]  110.44 39 90 bottom
R576  499-1-04  [M-R0402]  90.14 50.93 180 top
R577  499-1-04  [M-R0402]  109.22 134.14 180 bottom
R578  499-1-04  [M-R0402]  9.47 44.84 0 top
R579  499-1-04  [M-R0402]  9.47 43.63 0 top
R581  499-1-04  [M-R0402]  113.77 50.3 270 bottom
R582  499-1-04  [M-R0402]  115.04 50.3 270 bottom
R583  499-1-04  [M-R0402]  9.85 38.36 90 top
R584  499-1-04  [M-R0402]  113.74 55 90 bottom
R585  499-1-04  [M-R0402]  113.74 52.71 270 bottom
R586  499-1-04  [M-R0402]  115.01 52.71 270 bottom
R587  499-1-04  [M-R0402]  119.86 62.13 90 top
R588  499-1-04  [M-R0402]  120.94 62.13 90 top
R589  499-1-04  [M-R0402]  103.2 10.83 90 top
R590  499-1-04  [M-R0402]  103.2 11.72 270 top
R591  499-1-04  [M-R0402]  104.98 14.64 180 top
R592  499-1-04  [M-R0402]  102.69 14.59 0 top
R593  499-1-04  [M-R0402]  104.34 10.83 90 top
R594  499-1-04  [M-R0402]  104.34 11.72 270 top
R595  499-1-04  [M-R0402]  141.27 31.12 90 bottom
R596  499-1-04  [M-R0402]  18.56 104.07 90 top
R597  499-1-04  [M-R0402]  145.21 28.33 270 bottom
R598  499-1-04  [M-R0402]  149.53 24.94 180 bottom
R599  499-1-04  [M-R0402]  89.35 46.24 90 top
R600  499-1-04  [M-R0402]  131.74 104.27 180 bottom
R601  499-1-04  [M-R0402]  15.14 104.07 270 top
R602  499-1-04  [M-R0402]  130.02 103.66 270 bottom
R603  499-1-04  [M-R0402]  17.42 104.07 270 top
R604  499-1-04  [M-R0402]  16.28 104.07 270 top
R621  499-1-04  [M-R0402]  22.39 45.37 180 bottom
R622  499-1-04  [M-R0402]  20.09 45.52 0 top
R625  499-1-04  [M-R0402]  109.21 132.21 90 bottom
R637  VALUE*  [M-R0402]  107.98 132.21 270 bottom
R638  @1K-1-06  [M-R0603]  5.64 80.02 180 top
R639  499-1-04  [M-R0402]  52.85 138.99 0 top
R643  499-1-04  [M-R0402]  102.76 133.02 90 bottom
R645  499-1-04  [M-R0402]  55.97 138.86 270 top
R646  499-1-04  [M-R0402]  59.56 135.16 90 top
R647  499-1-04  [M-R0402]  22.32 44.35 0 top
R648  499-1-04  [M-R0402]  31.45 42.21 0 top
R650  VALUE*  [M-R0402]  101.56 133.02 270 bottom
R651  499-1-04  [M-R0402]  22.32 43.21 0 top
R653  499-1-04  [M-R0402]  103.97 135.24 90 bottom
R658  499-1-04  [M-R0402]  106.12 11.21 180 top
R660  499-1-04  [M-R0402]  59.15 61.37 270 top
R668  499-1-04  [M-R0402]  83.74 44.33 180 top
R669  499-1-04  [M-R0402]  92.4 50.94 0 top
R670  @1K-1-06  [M-R0603]  83.36 42.93 180 top
R671  @1K-1-06  [M-R0603]  89.35 42.3 90 top
R672  @1K-1-06  [M-R0603]  88.46 40.14 180 top
R687  499-1-04  [M-R0402]  60.2 61.37 270 top
R688  499-1-04  [M-R0402]  58.06 61.35 270 top
R689  499-1-04  [M-R0402]  57.96 58.93 270 bottom
R690  499-1-04  [M-R0402]  60.2 61.37 270 bottom
R691  499-1-04  [M-R0402]  59.15 61.37 270 bottom
R695  499-1-04  [M-R0402]  137.18 97.7 180 bottom
R696  499-1-04  [M-R0402]  140.02 97.61 180 bottom
R697  499-1-04  [M-R0402]  120.47 18.42 0 top
R698  499-1-04  [M-R0402]  121.61 12.71 0 top
R699  499-1-04  [M-R0402]  128.6 12.71 180 top
R700  499-1-04  [M-R0402]  123.9 11.57 180 top
R701  499-1-04  [M-R0402]  58.57 137.15 0 top
R710  499-1-04  [M-R0402]  126.31 11.57 0 top
R738  499-1-04  [M-R0402]  116.79 20.96 0 bottom
R739  499-1-04  [M-R0402]  116.79 19.82 0 bottom
R740  499-1-04  [M-R0402]  120.47 19.69 0 top
R741  499-1-04  [M-R0402]  120.47 21.98 0 top
R742  499-1-04  [M-R0402]  120.47 23.12 0 top
R743  499-1-04  [M-R0402]  116.79 17.54 0 bottom
R745  499-1-04  [M-R0402]  120.47 20.84 0 top
R784  499-1-04  [M-R0402]  122.66 25.15 180 top
R837  499-1-04  [M-R0402]  40.53 131.56 180 bottom
R838  499-1-04  [M-R0402]  40.53 130.42 0 bottom
R839  499-1-04  [M-R0402]  122.32 114.86 0 bottom
R840  499-1-04  [M-R0402]  40.53 129.27 0 bottom
R841  499-1-04  [M-R0402]  124.1 115.37 270 bottom
R842  499-1-04  [M-R0402]  42.25 129.85 90 bottom
R843  499-1-04  [M-R0402]  125.24 115.37 90 bottom
R844  499-1-04  [M-R0402]  122.32 113.72 180 bottom
R3058  499-1-04  [M-R0402]  80.21 61.86 180 top
R3085  499-1-04  [M-R0402]  82.5 61.86 0 top
R3087  499-1-04  [M-R0402]  79.32 61.86 0 top
R3095  499-1-04  [M-R0402]  83.38 61.86 180 top
R3152  499-1-04  [M-R0402]  85.29 61.35 90 top
R3153  499-1-04  [M-R0402]  83.13 67.95 90 bottom
R3154  499-1-04  [M-R0402]  81.61 67.95 90 bottom
R3160  499-1-04  [M-R0402]  22.32 42.06 0 top
R3161  499-1-04  [M-R0402]  20.34 40.25 270 top
R3163  499-1-04  [M-R0402]  68.65 79.38 180 bottom
R3164  499-1-04  [M-R0402]  70.68 71.13 0 bottom
R3197  499-1-04  [M-R0402]  96.97 136.78 270 bottom
R3198  499-1-04  [M-R0402]  95.83 136.78 270 bottom
R3201  499-1-04  [M-R0402]  104.65 138.82 270 bottom
R3214  499-1-04  [M-R0402]  103.32 63.89 180 bottom
R3232  499-1-04  [M-R0402]  86.43 61.35 90 top
R3239  499-1-04  [M-R0402]  81.23 12.58 0 top
R3243  499-1-04  [M-R0402]  81.23 11.44 0 top
R3247  499-1-04  [M-R0402]  89.1 4.45 270 bottom
R3248  499-1-04  [M-R0402]  89.52 2.38 180 bottom
R3249  499-1-04  [M-R0402]  89.1 11.69 0 top
R3250  499-1-04  [M-R0402]  86.69 71.33 180 bottom
R3251  499-1-04  [M-R0402]  86.71 70.14 180 bottom
R3252  499-1-04  [M-R0402]  89.07 12.92 0 top
R3253  499-1-04  [M-R0402]  91.8 2.38 180 bottom
R3255  499-1-04  [M-R0402]  59.25 69.61 0 bottom
R3258  499-1-04  [M-R0402]  59.25 70.75 180 bottom
R3278  499-1-04  [M-R0402]  10.7 50.57 270 top
R3279  499-1-04  [M-R0402]  13.75 50.57 270 top
R3280  499-1-04  [M-R0402]  12.48 50.57 270 top
R3281  499-1-04  [M-R0402]  9.3 50.57 270 top
R3294  499-1-04  [M-R0402]  25.6 29.35 0 top
R3310  499-1-04  [M-R0402]  25.6 26.3 180 top
R3321  499-1-04  [M-R0402]  24.53 77.71 90 top
R3322  499-1-04  [M-R0402]  26.95 76.76 0 top
R3323  499-1-04  [M-R0402]  29.89 76.74 0 top
R3370  499-1-04  [M-R0402]  25.6 27.44 180 top
R3386  499-1-04  [M-R0402]  25.6 30.49 0 top
R3401  499-1-04  [M-R0402]  24.42 51.21 0 top
R3402  499-1-04  [M-R0402]  27.22 50.73 90 top
R3403  499-1-04  [M-R0402]  22.32 47.72 180 bottom
R3405  499-1-04  [M-R0402]  24.42 50.07 0 top
R3406  @1K-1-06  [M-R0603]  56.98 43.36 0 top
R3407  499-1-04  [M-R0402]  22.32 48.86 180 bottom
R3408  499-1-04  [M-R0402]  26.45 49.68 270 bottom
R3409  499-1-04  [M-R0402]  27.45 47.17 270 bottom
R3410  499-1-04  [M-R0402]  25.31 49.56 270 bottom
R3413  499-1-04  [M-R0402]  20.02 43.17 0 top
R3414  499-1-04  [M-R0402]  20.09 44.37 0 top
R3415  499-1-04  [M-R0402]  24.16 43.08 270 bottom
R3416  @1K-1-06  [M-R0603]  61.16 37.6 270 top
R3417  499-1-04  [M-R0402]  30.44 49.83 0 bottom
R3421  499-1-04  [M-R0402]  17.36 51.1 0 top
R3422  499-1-04  [M-R0402]  17.36 50.03 0 top
R3425  @1K-1-06  [M-R0603]  47.06 36.59 0 top
R3426  499-1-04  [M-R0402]  28.47 50.72 90 top
R3428  499-1-04  [M-R0402]  24.47 41.07 180 bottom
R3429  499-1-04  [M-R0402]  24.47 39.8 180 top
R3430  499-1-04  [M-R0402]  27.71 41.33 0 bottom
R3431  499-1-04  [M-R0402]  19.2 50.47 90 top
R3432  @1K-1-06  [M-R0603]  45.79 50.37 180 top
R3433  499-1-04  [M-R0402]  22.39 43.21 180 bottom
R3434  499-1-04  [M-R0402]  22.12 38.66 0 top
R3436  499-1-04  [M-R0402]  21.61 40.25 90 top
R3437  @1K-1-06  [M-R0603]  30.25 68 180 bottom
R3439  499-1-04  [M-R0402]  26.82 37.45 180 top
R3440  499-1-04  [M-R0402]  26.81 40.78 180 top
R3442  499-1-04  [M-R0402]  27.96 38.47 180 top
R3443  @1K-1-06  [M-R0603]  38.12 67.55 90 top
R3444  499-1-04  [M-R0402]  25.29 38.66 180 bottom
R3445  499-1-04  [M-R0402]  25.29 39.74 0 bottom
R3446  499-1-04  [M-R0402]  25.29 37.64 180 bottom
R3447  @1K-1-06  [M-R0603]  72.46 38.11 90 top
R3448  @1K-1-06  [M-R0603]  75.76 34.93 270 top
R3449  499-1-04  [M-R0402]  20.79 38.6 0 bottom
R3450  499-1-04  [M-R0402]  19.9 39.67 0 bottom
R3451  499-1-04  [M-R0402]  19.91 40.82 180 bottom
R3527  499-1-04  [M-R0402]  22.39 42.06 180 bottom
RCH1  -  [M-R1206]  10.74 61.43 0 top
RT1  @1K-1-06  [M-R0603]  59.2 43.74 90 top
RT2  @1K-1-06  [M-R0603]  40.22 57.39 0 top
RT6  @1K-1-06  [M-R0603]  28.72 61.84 0 top
RT7  @1K-1-06  [M-R0603]  67.54 29.28 0 top
S1  @SCON2S  [SCON2S]  8.25 137.14 270 top
S2  @SCON2S  [SCON2S]  8.28 136.12 270 top
S3  @SCON2S  [SCON2S]  8.28 135.13 270 top
S4  @SCON2S  [SCON2S]  8.25 133.13 270 top
S5  @SCON2S  [SCON2S]  8.25 132.16 270 top
S6  @SCON2S  [SCON2S]  8.28 131.14 270 top
S7  @SCON2S  [SCON2S]  8.25 130.13 270 top
S8  @SCON2S  [SCON2S]  8.25 129.16 270 top
S9  @SCON2S  [SCON2S]  8.28 128.17 270 top
S10  @SCON2S  [SCON2S]  8.28 127.16 270 top
S11  @SCON2S  [SCON2S]  8.28 126.14 270 top
S12  @SCON2S  [SCON2S]  8.28 125.12 270 top
S13  @SCON2S  [SCON2S]  8.28 124.13 270 top
S14  @SCON2S  [SCON2S]  8.28 123.17 270 top
S15  @SCON2S  [SCON2S]  8.25 122.15 270 top
S16  @SCON2S  [SCON2S]  8.25 121.14 270 top
S17  @SCON2S  [SCON2S]  8.25 120.15 270 top
S18  @SCON2S  [SCON2S]  8.25 134.14 270 top
S19  @SCON2S  [SCON2S]  8.25 119.16 270 top
S20  @SCON2S  [SCON2S]  8.25 118.14 270 top
S21  @SCON2S  [SCON2S]  8.28 117.15 270 top
S22  @SCON2S  [SCON2S]  8.25 116.13 270 top
S23  @SCON2S  [SCON2S]  8.25 114.15 270 top
S24  @SCON2S  [SCON2S]  8.25 115.17 270 top
S25  @SCON2S  [SCON2S]  16.94 57.99 0 top
S26  @SCON2S  [SCON2S]  18.19 58.01 0 top
S27  @SCON2S  [SCON2S]  19.42 57.98 0 top
S28  @SCON2S  [SCON2S]  20.69 58.01 0 top
S31  @SCON2S  [SCON2S]  139.29 15.43 0 top
S32  @SCON2S  [SCON2S]  140.48 15.43 0 top
S33  @SCON2S  [SCON2S]  140.76 125.36 270 top
S34  @SCON2S  [SCON2S]  141.65 125.36 90 top
S35  @SCON2S  [SCON2S]  141.85 15.43 0 top
S36  @SCON2S  [SCON2S]  141.27 39.12 0 top
S37  @SCON2S  [SCON2S]  143.07 15.43 0 top
S38  @SCON2S  [SCON2S]  141.2 31.63 0 top
S39  @SCON2S  [SCON2S]  140.99 45.24 0 top
S40  @SCON2S  [SCON2S]  141.35 43.62 0 top
S41  @SCON2S  [SCON2S]  141.04 27.79 180 top
S42  @SCON2S  [SCON2S]  140.38 30.26 180 top
S43  @SCON2S  [SCON2S]  141.2 25.15 0 top
S44  @SCON2S  [SCON2S]  147.29 61.05 180 top
S45  @SCON2S  [SCON2S]  147.32 57.47 0 top
S46  @SCON2S  [SCON2S]  147.34 79.08 180 top
S47  @SCON2S  [SCON2S]  147.32 75.42 0 top
S48  @SCON2S  [SCON2S]  134.33 137.42 90 bottom
S49  @SCON2S  [SCON2S]  148.82 120.91 0 bottom
S50  @SCON2S  [SCON2S]  148.82 117.44 180 bottom
S51  @SCON2S  [SCON2S]  147.86 116.74 225 bottom
S52  @SCON2S  [SCON2S]  148.82 113.48 180 bottom
S53  @SCON2S  [SCON2S]  147.32 114.42 180 bottom
S54  @SCON2S  [SCON2S]  148.82 111.45 180 bottom
SBCN1  @FFC,JXT,FP243A-012G10M,12P0.5H1.2,S  [CON12-2_0D5_50501ACES]  101.54 4.41 0 top
SBCN2  -  [CON_FFC-DYS-W003-14P_D5]  113.41 3.56 0 top
SPK1  WB,ET,3801K-Q04N-07L,4P,SMT,P1.25  [CON_WB_4H125_50278-0040N_ACES]  141.15 11.52 0 top
SW1  SWITCH,STS-A87SNZ1-MX,6P,H=1.5,CTI  [SWITCH_T-V_TME-533K-Q-TR_DIP]  133.19 134.3 0 bottom
TA1  -  [VIA16]  27.01 97.27 0 top
TA2  -  [VIA16]  27.45 96.38 0 top
TA3  -  [VIA16]  25.13 97.63 270 top
TA4  -  [VIA16]  28.56 98.2 270 top
TA5  -  [VIA16]  29.8 95.75 270 top
TA6  -  [VIA16]  26.37 98.73 270 top
TA7  -  [VIA16]  34.69 100.25 270 top
TA8  -  [VIA16]  28.03 96.38 270 top
TA9  -  [VIA16]  24.87 96.49 270 top
TA10  -  [VIA16]  31.39 99.81 270 top
TA11  -  [VIA16]  30.44 97.84 270 top
TA12  -  [VIA16]  26.95 98.67 270 top
TA13  -  [VIA16]  29.51 99.09 270 top
TA14  -  [VIA16]  29.3 96.38 270 top
TA15  -  [VIA16]  33.11 96.89 0 top
TA16  -  [VIA16]  28.15 95.43 270 top
TA17  -  [VIA16]  31.64 98.35 270 top
TA18  -  [VIA16]  25.51 98.26 270 top
TA19  -  [VIA16]  34.06 100.25 270 top
TA20  -  [VIA16]  35.26 94.88 270 top
TA21  -  [VIA16]  30.88 95.94 270 top
TA22  -  [VIA16]  36.41 101.02 270 top
TA23  -  [VIA16]  25.76 97.18 270 top
TA24  -  [VIA16]  32.15 98.35 270 top
TA25  -  [VIA16]  37.38 95.98 270 top
TA26  -  [VIA16]  36.82 95.98 270 top
TA28  -  [VIA16]  34.95 97.59 270 top
TA29  -  [VIA16]  33.07 95.49 270 top
TB1  -  [VIA16]  28.24 87.89 270 top
TB2  -  [VIA16]  27.48 88.53 270 top
TB3  -  [VIA16]  25.95 87.89 270 top
TB4  -  [VIA16]  30.52 87.89 270 top
TB5  -  [VIA16]  29 88.53 270 top
TB6  -  [VIA16]  33.83 89.23 270 top
TB7  -  [VIA16]  26.71 88.53 270 top
TB8  -  [VIA16]  25.17 88.55 270 top
TB9  -  [VIA16]  28.24 88.53 270 top
TB10  -  [VIA16]  30.52 88.53 270 top
TB11  -  [VIA16]  31.54 88.53 270 top
TB12  -  [VIA16]  29.76 88.53 270 top
TB13  -  [VIA16]  27.48 87.89 270 top
TB14  -  [VIA16]  33.06 88.48 270 top
TB15  -  [VIA16]  29.76 87.89 270 top
TB16  -  [VIA16]  32.3 87.89 270 top
TB17  -  [VIA16]  29 87.89 270 top
TB18  -  [VIA16]  34.91 87.53 270 top
TB19  -  [VIA16]  25.95 88.53 270 top
TB20  -  [VIA16]  31.54 87.89 270 top
TB21  -  [VIA16]  33.8 88.12 270 top
TB22  -  [VIA16]  26.71 87.89 270 top
TB23  -  [VIA16]  34.91 88.23 270 top
TB24  -  [VIA16]  32.3 88.5 270 top
TB25  -  [VIA16]  36.11 87.98 270 top
TB26  -  [VIA16]  35.6 87.98 270 top
TB27  -  [VIA16]  34.75 88.99 270 top
TB29  -  [VIA16]  33.76 87.53 270 top
TC1  -  [VIA16]  28.24 106.43 270 top
TC2  -  [VIA16]  27.48 107.07 270 top
TC3  -  [VIA16]  25.95 106.43 270 top
TC4  -  [VIA16]  30.52 106.43 270 top
TC5  -  [VIA16]  29 107.07 270 top
TC6  -  [VIA16]  33.74 107.75 270 top
TC7  -  [VIA16]  26.71 107.07 270 top
TC8  -  [VIA16]  25.19 107.07 270 top
TC9  -  [VIA16]  28.24 107.07 270 top
TC10  -  [VIA16]  30.52 107.07 270 top
TC11  -  [VIA16]  31.54 107.07 270 top
TC12  -  [VIA16]  29.76 107.07 270 top
TC13  -  [VIA16]  27.48 106.43 270 top
TC14  -  [VIA16]  33.04 107.07 270 top
TC15  -  [VIA16]  29.76 106.43 270 top
TC16  -  [VIA16]  32.3 106.43 270 top
TC17  -  [VIA16]  29 106.43 270 top
TC18  -  [VIA16]  34.91 106.07 270 top
TC19  -  [VIA16]  25.95 107.07 270 top
TC20  -  [VIA16]  31.54 106.43 270 top
TC21  -  [VIA16]  33.83 106.65 270 top
TC22  -  [VIA16]  34.91 106.77 270 top
TC23  -  [VIA16]  26.71 106.43 270 top
TC24  -  [VIA16]  32.3 107.07 270 top
TC25  -  [VIA16]  36.11 106.54 270 top
TC26  -  [VIA16]  35.6 106.51 270 top
TC27  -  [VIA16]  32.28 92.7 180 bottom
TC28  -  [VIA16]  34.91 107.34 270 top
TC29  -  [VIA16]  33.78 106.07 270 top
TC30  -  [VIA16]  31.64 83.24 0 top
TC31  -  [VIA16]  31.73 101.63 180 bottom
TC32  -  [VIA16]  32.49 111.73 0 top
TP1  -  [TP12T]  27.73 108.93 270 top
TP2  -  [TP12T]  8.84 40.9 270 top
TP3  -  [TP12T]  8.9 41.78 270 top
TP4  -  [TP12T]  56.69 63.38 0 top
TP5  -  [TP12T]  56.99 87.69 0 top
TP6  -  [TP12T]  57.63 87.66 0 top
TP7  -  [TP12T]  64.31 62.11 0 top
TP8  -  [TP12T]  64.31 61.48 0 top
TP9  -  [TP12T]  64.31 60.84 0 top
TP10  -  [TP12T]  64.31 60.21 0 top
TP11  -  [TP12T]  64.31 59.57 0 top
TP12  -  [TP12T]  68.75 62.11 0 top
TP13  -  [TP12T]  68.75 61.48 0 top
TP14  -  [TP12T]  68.75 60.84 0 top
TP15  -  [TP12T]  68.75 60.08 270 top
TP16  -  [TP12T]  76.24 61.98 0 top
TP17  -  [TP12T]  76.24 61.35 0 top
TP18  -  [TP12T]  91.76 91.52 0 top
TP19  -  [TP12T]  98.72 62.11 0 top
TP20  -  [TP12T]  98.72 61.35 0 top
TP21  -  [TP12T]  104.01 87.84 0 top
TP23  -  [TP12T]  105.33 65.29 0 top
TP24  -  [TP12T]  104.57 87.84 0 top
TP26  -  [TP12T]  105.96 65.29 0 top
TP27  -  [TP12T]  105.12 87.84 0 top
TP28  -  [TP12T]  107.21 84.54 0 top
TP29  -  [TP12T]  107.61 84.59 0 top
TP33  -  [TP12T]  100.25 96.4 180 bottom
TP34  -  [TP12T]  99.61 96.4 180 bottom
TP35  -  [TP12T]  58.92 87.69 180 bottom
TP36  -  [TP12T]  58.26 87.69 180 bottom
TP37  -  [TP12T]  62.2 87.31 180 bottom
TP38  -  [TP12T]  61.51 86.72 180 bottom
TP39  -  [TP12T]  99.08 86.09 180 bottom
TP40  -  [TP12T]  60.88 86.09 180 bottom
TP41  -  [TP12T]  97.89 85.12 180 bottom
TP42  -  [TP12T]  94.23 85.12 180 bottom
TP43  -  [TP12T]  97.89 84.49 180 bottom
TP45  -  [TP12T]  95.14 83.85 180 bottom
TP46  -  [TP12T]  53.93 138.54 0 top
TP47  -  [TP12T]  93.36 83.22 180 bottom
TP48  -  [TP12T]  93.36 82.58 180 bottom
TP49  -  [TP12T]  94.28 82.56 180 bottom
TP50  -  [TP12T]  95.14 81.95 180 bottom
TP51  -  [TP12T]  64.97 81.95 180 bottom
TP52  -  [TP12T]  87.83 81.92 180 bottom
TP53  -  [TP12T]  86.91 81.92 180 bottom
TP54  -  [TP12T]  101.62 81.39 180 bottom
TP55  -  [TP12T]  94.71 81.03 180 bottom
TP56  -  [TP12T]  94.08 81.01 180 bottom
TP57  -  [TP12T]  94.79 80.14 180 bottom
TP58  -  [TP12T]  67.35 80.12 180 bottom
TP59  -  [TP12T]  66.57 80.09 180 bottom
TP60  -  [TP12T]  67.38 79.33 180 bottom
TP61  -  [TP12T]  63.54 78.37 180 bottom
TP62  -  [TP12T]  65.25 77.33 180 bottom
TP63  -  [TP12T]  65.25 76.44 180 bottom
TP64  -  [TP12T]  95.35 72.65 180 bottom
TP65  -  [TP12T]  94.71 72.65 180 bottom
TP66  -  [TP12T]  96.67 73.21 180 bottom
TP67  -  [TP12T]  97.61 73 180 bottom
TP68  -  [TP12T]  97.89 69.68 0 bottom
TP69  -  [TP12T]  96.06 67.78 180 bottom
TP70  -  [TP12T]  65.96 64.07 90 bottom
TP71  -  [TP12T]  68.37 64.27 180 bottom
TP72  -  [TP12T]  67.38 63.51 90 bottom
TP73  -  [TP12T]  98.32 71.28 180 bottom
TP74  -  [TP12T]  92.66 91.58 0 top
TP75  -  [TP12T]  124.04 6.34 180 bottom
TP76  -  [TP12T]  125.05 6.34 180 bottom
TP77  -  [TP12T]  158.16 37.37 180 bottom
TP78  -  [TP12T]  151.58 31.09 180 bottom
TP79  -  [TP12T]  105.1 80.27 0 top
TP80  -  [TP12T]  25.55 117.02 0 top
TP81  -  [TP12T]  104.09 79.05 0 top
TP82  -  [TP12T]  104.09 78.37 0 top
TP83  -  [TP12T]  26.57 117.93 180 top
TP84  -  [TP12T]  104.47 80.27 0 top
TP183  -  [TP20]  76.27 2.42 180 bottom
TP184  -  [TP20]  78.43 2.42 180 bottom
TP185  -  [TP20]  85.04 2.3 180 bottom
TP186  -  [TP20]  85.8 2.3 180 bottom
TP187  -  [TP20]  86.56 2.3 180 bottom
TP188  -  [TP20]  87.32 2.3 180 bottom
TP189  -  [TP20]  24.2 17.28 0 top
TP190  -  [TP20]  23.95 31.63 0 top
TP200  -  [TP20]  12.9 16.01 0 top
TP201  -  [TP20]  12.9 17.03 0 top
TP209  -  [TP20]  24.2 28.46 0 top
U1  OZ8692LN  [VQFN40-3_0D4_5D0X5D0MCM]  14.57 94.55 0 top
U2  -  [M-SO8]  16.05 109.35 270 top
U3  -  [M-SOP8B]  16.43 124.85 0 top
U4  -  [DFN3X2-14L]  27.48 125.74 180 top
U5  -  [DFN3X2-14L]  32.91 127.19 270 top
U8  -  [M-SO8_EP]  39.27 121.72 270 top
U9  RT7291A/B  [UQFN16_0D4_3X3]  40.76 134.61 180 top
U11  -  [SKL_42X24_P65_1356]  80.69 76.59 0 top
U12  PWR_RT8237E  [DFN3-10EP_0-5_2]  86.91 44.46 180 top
U13  GS9271DTQ-R  [TQFN32-2_4X4_GS9271]  95.5 137.27 180 top
U14  -  [DFN3X2-14L]  99.36 52.46 0 top
U15  -  [M-SOT23-5]  118.79 95.64 90 top
U18  RT7291A/B  [UQFN16_0D4_3X3]  124.03 115.2 270 top
U19  -  [LGA16_3X3_D5]  129.58 63.89 0 top
U20  -  [M-SOP8B]  131.08 87.08 0 top
U23  -  [M-SO8_EP]  140.48 73.59 180 top
U25  -  [QFPS128-04M-60]  16.05 123.32 180 bottom
U26  -  [M-MSOP8]  141.09 115.12 180 bottom
U28  @NPCT420DA0WX  [M-TSSOP28-0_65-6_4MM]  13.91 105.6 90 bottom
U31  -  [SOT-23-5]  16.94 70.47 90 top
U32  -  [TSOT23-8]  55.13 136.15 270 top
U33  Realtek,Codec,ALC269Q-VC3-GR  [QFN48_D4-6X6]  151.86 35.41 180 bottom
U109  OZ8283LN  [QFN40-1_0D4_5D0X5D0_OZ8283]  26.58 45.11 0 top
U110  OZ8002LN  [QFN16-1_0D4_2D5X2D5_OZ8002]  35.74 52.74 270 top
U1634  NFC_NPC100  [BGA_49_0D5_4D1X4D4]  125.57 19.45 0 top
U1635  val  [FBGA96_0D8_16X9_DDR4SDRAM]  35.73 88.15 90 bottom
U1636  val  [FBGA96_0D8_16X9_DDR4SDRAM]  35.73 88.15 270 top
U1637  val  [FBGA96_0D8_16X9_DDR4SDRAM]  35.73 106.69 270 top
U1638  val  [FBGA96_0D8_16X9_DDR4SDRAM]  35.73 106.69 90 bottom
USB2R1  -  [CON4-4_0D7_2D0_USB_A0315]  156.02 77.26 90 top
USB2R2  -  [CON4-4_0D7_2D0_USB_A0315]  156.02 59.26 90 top
USB3R1  -  [CON_SUSB_3SR_UEA1111-R04012_FOX]  148.82 116.2 90 top
WIFI1  -  [RL-UM02WBS-8723BU-1]  117.24 43.34 180 top
Y1  -  [SMD_CRYSTAL-TXC-4P_3D2X2D5]  80.44 58.3 0 top
Y3  -  [XTAL_CS3215_2P]  91.99 93.99 180 bottom
Y6  -  [SMD_CRYSTAL-TXC-4P_3D2X2D5]  122.66 27.43 180 top

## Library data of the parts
